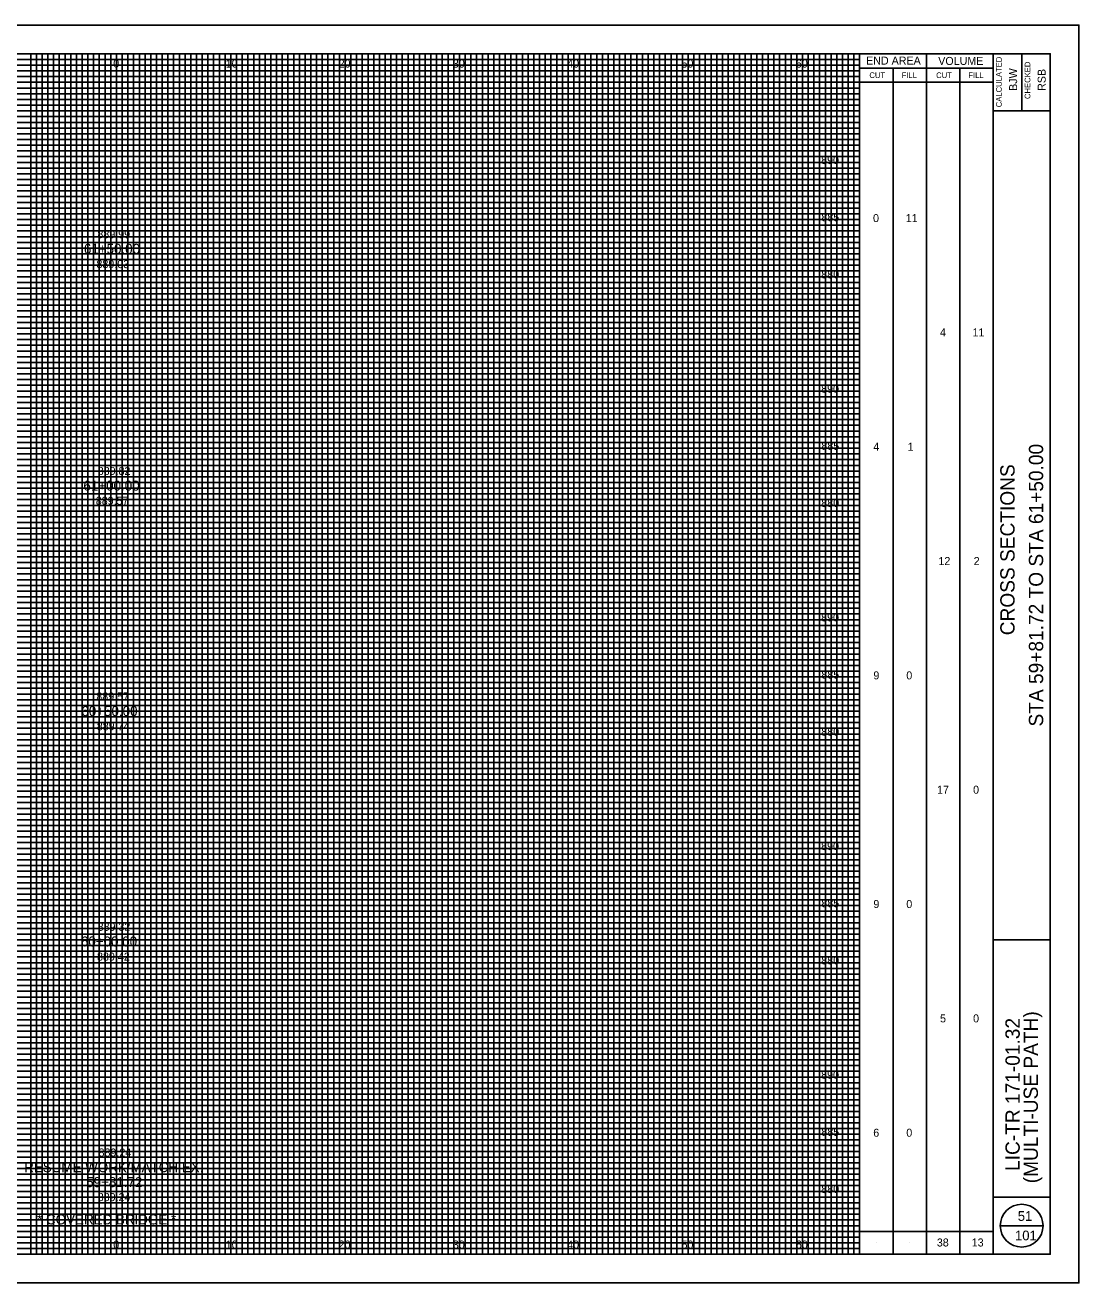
# Model space of a CAD drawing. Extents: x -10 to 160, y -2 to 222.
# Drawn here: x 67.8 to 160, y -2.5 to 107.5 of the extents above; entities that cross this region are included whole.
import ezdxf

# ---------------------------------------------------------------- set-up
doc = ezdxf.new("R2010")
doc.units = 0
for name, color, linetype in [('GK_Cells', 7, 'Continuous'), ('GK_Patterns', 7, 'Continuous'), ('SH_Cut_Line', 7, 'Continuous'), ('TX_P_10', 7, 'Continuous'), ('TX_X_10', 7, 'Continuous'), ('XS_P_Pavt_Surface', 7, 'Continuous'), ('XS_P_Text_Info', 7, 'Continuous'), ('XS_X_Ground_Line', 7, 'Continuous')]:
    doc.layers.add(name, color=color, linetype=linetype)

msp = doc.modelspace()

# ---------------------------------------------------------------- linework, layer by layer
at = {"layer": 'GK_Cells'}
msp.add_lwpolyline([(-10, -2.5), (160, -2.5), (160, 107.5), (-10, 107.5)], close=True, dxfattribs=at)
at = {"layer": 'TX_P_10'}
for p, q in [((140.83, 0), (140.83, 105)), ((146.67, 0), (146.67, 105)), ((140.83, 103.75), (152.5, 103.75)), ((143.75, 0), (143.75, 103.75)), ((149.58, 0), (149.58, 103.75)), ((140.83, 102.5), (152.5, 102.5)), ((153.12, 2.5), (156.88, 2.5)), ((140.83, 2), (152.5, 2)), ((142.29, 1), (142.29, 1)), ((145.21, 1), (145.21, 1)), ((148.12, 1), (148.12, 1)), ((151.04, 1), (151.04, 1))]:
    msp.add_line(p, q, dxfattribs=at)
msp.add_circle((155, 2.5), 1.87, dxfattribs=at)
at = {"layer": 'TX_X_10'}
for p, q in [((70.83, 0), (70.83, 105)), ((75.83, 0), (75.83, 105)), ((80.83, 0), (80.83, 105)), ((85.83, 0), (85.83, 105)), ((90.83, 0), (90.83, 105)), ((95.83, 0), (95.83, 105)), ((100.83, 0), (100.83, 105)), ((105.83, 0), (105.83, 105)), ((110.83, 0), (110.83, 105)), ((115.83, 0), (115.83, 105)), ((120.83, 0), (120.83, 105)), ((125.83, 0), (125.83, 105)), ((130.83, 0), (130.83, 105)), ((135.83, 0), (135.83, 105)), ((5.83, 100), (140.83, 100)), ((5.83, 95), (140.83, 95)), ((5.83, 90), (140.83, 90)), ((5.83, 85), (140.83, 85)), ((5.83, 80), (140.83, 80)), ((5.83, 75), (140.83, 75)), ((5.83, 70), (140.83, 70)), ((5.83, 65), (140.83, 65)), ((5.83, 60), (140.83, 60)), ((5.83, 55), (140.83, 55)), ((5.83, 50), (140.83, 50)), ((5.83, 45), (140.83, 45)), ((5.83, 40), (140.83, 40)), ((5.83, 35), (140.83, 35)), ((5.83, 30), (140.83, 30)), ((5.83, 25), (140.83, 25)), ((5.83, 20), (140.83, 20)), ((5.83, 15), (140.83, 15)), ((5.83, 10), (140.83, 10)), ((5.83, 5), (140.83, 5))]:
    msp.add_line(p, q, dxfattribs=at)
at = {"layer": 'XS_P_Pavt_Surface'}
for p, q in [((152.5, 0), (152.5, 105)), ((155, 105), (155, 100)), ((152.5, 100), (157.5, 100)), ((152.5, 27.5), (157.5, 27.5)), ((152.5, 5), (157.5, 5))]:
    msp.add_line(p, q, dxfattribs=at)
msp.add_lwpolyline([(0, 105), (157.5, 105), (157.5, 0), (0, 0)], close=True, dxfattribs=at)
at = {"layer": 'XS_X_Ground_Line'}
for p, q in [((68.33, 0), (68.33, 105)), ((68.83, 0), (68.83, 105)), ((69.33, 0), (69.33, 105)), ((69.83, 0), (69.83, 105)), ((70.33, 0), (70.33, 105)), ((71.33, 0), (71.33, 105)), ((71.83, 0), (71.83, 105)), ((72.33, 0), (72.33, 105)), ((72.83, 0), (72.83, 105)), ((73.33, 0), (73.33, 105)), ((73.83, 0), (73.83, 105)), ((74.33, 0), (74.33, 105)), ((74.83, 0), (74.83, 105)), ((75.33, 0), (75.33, 105)), ((76.33, 0), (76.33, 105)), ((76.83, 0), (76.83, 105)), ((77.33, 0), (77.33, 105)), ((77.83, 0), (77.83, 105)), ((78.33, 0), (78.33, 105)), ((78.83, 0), (78.83, 105)), ((79.33, 0), (79.33, 105)), ((79.83, 0), (79.83, 105)), ((80.33, 0), (80.33, 105)), ((81.33, 0), (81.33, 105)), ((81.83, 0), (81.83, 105)), ((82.33, 0), (82.33, 105)), ((82.83, 0), (82.83, 105)), ((83.33, 0), (83.33, 105)), ((83.83, 0), (83.83, 105)), ((84.33, 0), (84.33, 105)), ((84.83, 0), (84.83, 105)), ((85.33, 0), (85.33, 105)), ((86.33, 0), (86.33, 105)), ((86.83, 0), (86.83, 105)), ((87.33, 0), (87.33, 105)), ((87.83, 0), (87.83, 105)), ((88.33, 0), (88.33, 105)), ((88.83, 0), (88.83, 105)), ((89.33, 0), (89.33, 105)), ((89.83, 0), (89.83, 105)), ((90.33, 0), (90.33, 105)), ((91.33, 0), (91.33, 105)), ((91.83, 0), (91.83, 105)), ((92.33, 0), (92.33, 105)), ((92.83, 0), (92.83, 105)), ((93.33, 0), (93.33, 105)), ((93.83, 0), (93.83, 105)), ((94.33, 0), (94.33, 105)), ((94.83, 0), (94.83, 105)), ((95.33, 0), (95.33, 105)), ((96.33, 0), (96.33, 105)), ((96.83, 0), (96.83, 105)), ((97.33, 0), (97.33, 105)), ((97.83, 0), (97.83, 105)), ((98.33, 0), (98.33, 105)), ((98.83, 0), (98.83, 105)), ((99.33, 0), (99.33, 105)), ((99.83, 0), (99.83, 105)), ((100.33, 0), (100.33, 105)), ((101.33, 0), (101.33, 105)), ((101.83, 0), (101.83, 105)), ((102.33, 0), (102.33, 105)), ((102.83, 0), (102.83, 105)), ((103.33, 0), (103.33, 105)), ((103.83, 0), (103.83, 105)), ((104.33, 0), (104.33, 105)), ((104.83, 0), (104.83, 105)), ((105.33, 0), (105.33, 105)), ((106.33, 0), (106.33, 105)), ((106.83, 0), (106.83, 105)), ((107.33, 0), (107.33, 105)), ((107.83, 0), (107.83, 105)), ((108.33, 0), (108.33, 105)), ((108.83, 0), (108.83, 105)), ((109.33, 0), (109.33, 105)), ((109.83, 0), (109.83, 105)), ((110.33, 0), (110.33, 105)), ((111.33, 0), (111.33, 105)), ((111.83, 0), (111.83, 105)), ((112.33, 0), (112.33, 105)), ((112.83, 0), (112.83, 105)), ((113.33, 0), (113.33, 105)), ((113.83, 0), (113.83, 105)), ((114.33, 0), (114.33, 105)), ((114.83, 0), (114.83, 105)), ((115.33, 0), (115.33, 105)), ((116.33, 0), (116.33, 105)), ((116.83, 0), (116.83, 105)), ((117.33, 0), (117.33, 105)), ((117.83, 0), (117.83, 105)), ((118.33, 0), (118.33, 105)), ((118.83, 0), (118.83, 105)), ((119.33, 0), (119.33, 105)), ((119.83, 0), (119.83, 105)), ((120.33, 0), (120.33, 105)), ((121.33, 0), (121.33, 105)), ((121.83, 0), (121.83, 105)), ((122.33, 0), (122.33, 105)), ((122.83, 0), (122.83, 105)), ((123.33, 0), (123.33, 105)), ((123.83, 0), (123.83, 105)), ((124.33, 0), (124.33, 105)), ((124.83, 0), (124.83, 105)), ((125.33, 0), (125.33, 105)), ((126.33, 0), (126.33, 105)), ((126.83, 0), (126.83, 105)), ((127.33, 0), (127.33, 105)), ((127.83, 0), (127.83, 105)), ((128.33, 0), (128.33, 105)), ((128.83, 0), (128.83, 105)), ((129.33, 0), (129.33, 105)), ((129.83, 0), (129.83, 105)), ((130.33, 0), (130.33, 105)), ((131.33, 0), (131.33, 105)), ((131.83, 0), (131.83, 105)), ((132.33, 0), (132.33, 105)), ((132.83, 0), (132.83, 105)), ((133.33, 0), (133.33, 105)), ((133.83, 0), (133.83, 105)), ((134.33, 0), (134.33, 105)), ((134.83, 0), (134.83, 105)), ((135.33, 0), (135.33, 105)), ((136.33, 0), (136.33, 105)), ((136.83, 0), (136.83, 105)), ((137.33, 0), (137.33, 105)), ((137.83, 0), (137.83, 105)), ((138.33, 0), (138.33, 105)), ((138.83, 0), (138.83, 105)), ((139.33, 0), (139.33, 105)), ((139.83, 0), (139.83, 105)), ((140.33, 0), (140.33, 105)), ((5.83, 104.5), (140.83, 104.5)), ((5.83, 104), (140.83, 104)), ((5.83, 103.5), (140.83, 103.5)), ((5.83, 103), (140.83, 103)), ((5.83, 102.5), (140.83, 102.5)), ((5.83, 102), (140.83, 102)), ((5.83, 101.5), (140.83, 101.5)), ((5.83, 101), (140.83, 101)), ((5.83, 100.5), (140.83, 100.5)), ((5.83, 99.5), (140.83, 99.5)), ((5.83, 99), (140.83, 99)), ((5.83, 98.5), (140.83, 98.5)), ((5.83, 98), (140.83, 98)), ((5.83, 97.5), (140.83, 97.5)), ((5.83, 97), (140.83, 97)), ((5.83, 96.5), (140.83, 96.5)), ((5.83, 96), (140.83, 96)), ((5.83, 95.5), (140.83, 95.5)), ((5.83, 94.5), (140.83, 94.5)), ((5.83, 94), (140.83, 94)), ((5.83, 93.5), (140.83, 93.5)), ((5.83, 93), (140.83, 93)), ((5.83, 92.5), (140.83, 92.5)), ((5.83, 92), (140.83, 92)), ((5.83, 91.5), (140.83, 91.5)), ((5.83, 91), (140.83, 91)), ((5.83, 90.5), (140.83, 90.5)), ((5.83, 89.5), (140.83, 89.5)), ((5.83, 89), (140.83, 89)), ((5.83, 88.5), (140.83, 88.5)), ((5.83, 88), (140.83, 88)), ((5.83, 87.5), (140.83, 87.5)), ((5.83, 87), (140.83, 87)), ((5.83, 86.5), (140.83, 86.5)), ((5.83, 86), (140.83, 86)), ((5.83, 85.5), (140.83, 85.5)), ((5.83, 84.5), (140.83, 84.5)), ((5.83, 84), (140.83, 84)), ((5.83, 83.5), (140.83, 83.5)), ((5.83, 83), (140.83, 83)), ((5.83, 82.5), (140.83, 82.5)), ((5.83, 82), (140.83, 82)), ((5.83, 81.5), (140.83, 81.5)), ((5.83, 81), (140.83, 81)), ((5.83, 80.5), (140.83, 80.5)), ((5.83, 79.5), (140.83, 79.5)), ((5.83, 79), (140.83, 79)), ((5.83, 78.5), (140.83, 78.5)), ((5.83, 78), (140.83, 78)), ((5.83, 77.5), (140.83, 77.5)), ((5.83, 77), (140.83, 77)), ((5.83, 76.5), (140.83, 76.5)), ((5.83, 76), (140.83, 76)), ((5.83, 75.5), (140.83, 75.5)), ((5.83, 74.5), (140.83, 74.5)), ((5.83, 74), (140.83, 74)), ((5.83, 73.5), (140.83, 73.5)), ((5.83, 73), (140.83, 73)), ((5.83, 72.5), (140.83, 72.5)), ((5.83, 72), (140.83, 72)), ((5.83, 71.5), (140.83, 71.5)), ((5.83, 71), (140.83, 71)), ((5.83, 70.5), (140.83, 70.5)), ((5.83, 69.5), (140.83, 69.5)), ((5.83, 69), (140.83, 69)), ((5.83, 68.5), (140.83, 68.5)), ((5.83, 68), (140.83, 68)), ((5.83, 67.5), (140.83, 67.5)), ((5.83, 67), (140.83, 67)), ((5.83, 66.5), (140.83, 66.5)), ((5.83, 66), (140.83, 66)), ((5.83, 65.5), (140.83, 65.5)), ((5.83, 64.5), (140.83, 64.5)), ((5.83, 64), (140.83, 64)), ((5.83, 63.5), (140.83, 63.5)), ((5.83, 63), (140.83, 63)), ((5.83, 62.5), (140.83, 62.5)), ((5.83, 62), (140.83, 62)), ((5.83, 61.5), (140.83, 61.5)), ((5.83, 61), (140.83, 61)), ((5.83, 60.5), (140.83, 60.5)), ((5.83, 59.5), (140.83, 59.5)), ((5.83, 59), (140.83, 59)), ((5.83, 58.5), (140.83, 58.5)), ((5.83, 58), (140.83, 58)), ((5.83, 57.5), (140.83, 57.5)), ((5.83, 57), (140.83, 57)), ((5.83, 56.5), (140.83, 56.5)), ((5.83, 56), (140.83, 56)), ((5.83, 55.5), (140.83, 55.5)), ((5.83, 54.5), (140.83, 54.5)), ((5.83, 54), (140.83, 54)), ((5.83, 53.5), (140.83, 53.5)), ((5.83, 53), (140.83, 53)), ((5.83, 52.5), (140.83, 52.5)), ((5.83, 52), (140.83, 52)), ((5.83, 51.5), (140.83, 51.5)), ((5.83, 51), (140.83, 51)), ((5.83, 50.5), (140.83, 50.5)), ((5.83, 49.5), (140.83, 49.5)), ((5.83, 49), (140.83, 49)), ((5.83, 48.5), (140.83, 48.5)), ((5.83, 48), (140.83, 48)), ((5.83, 47.5), (140.83, 47.5)), ((5.83, 47), (140.83, 47)), ((5.83, 46.5), (140.83, 46.5)), ((5.83, 46), (140.83, 46)), ((5.83, 45.5), (140.83, 45.5)), ((5.83, 44.5), (140.83, 44.5)), ((5.83, 44), (140.83, 44)), ((5.83, 43.5), (140.83, 43.5)), ((5.83, 43), (140.83, 43)), ((5.83, 42.5), (140.83, 42.5)), ((5.83, 42), (140.83, 42)), ((5.83, 41.5), (140.83, 41.5)), ((5.83, 41), (140.83, 41)), ((5.83, 40.5), (140.83, 40.5)), ((5.83, 39.5), (140.83, 39.5)), ((5.83, 39), (140.83, 39)), ((5.83, 38.5), (140.83, 38.5)), ((5.83, 38), (140.83, 38)), ((5.83, 37.5), (140.83, 37.5)), ((5.83, 37), (140.83, 37)), ((5.83, 36.5), (140.83, 36.5)), ((5.83, 36), (140.83, 36)), ((5.83, 35.5), (140.83, 35.5)), ((5.83, 34.5), (140.83, 34.5)), ((5.83, 34), (140.83, 34)), ((5.83, 33.5), (140.83, 33.5)), ((5.83, 33), (140.83, 33)), ((5.83, 32.5), (140.83, 32.5)), ((5.83, 32), (140.83, 32)), ((5.83, 31.5), (140.83, 31.5)), ((5.83, 31), (140.83, 31)), ((5.83, 30.5), (140.83, 30.5)), ((5.83, 29.5), (140.83, 29.5)), ((5.83, 29), (140.83, 29)), ((5.83, 28.5), (140.83, 28.5)), ((5.83, 28), (140.83, 28)), ((5.83, 27.5), (140.83, 27.5)), ((5.83, 27), (140.83, 27)), ((5.83, 26.5), (140.83, 26.5)), ((5.83, 26), (140.83, 26)), ((5.83, 25.5), (140.83, 25.5)), ((5.83, 24.5), (140.83, 24.5)), ((5.83, 24), (140.83, 24)), ((5.83, 23.5), (140.83, 23.5)), ((5.83, 23), (140.83, 23)), ((5.83, 22.5), (140.83, 22.5)), ((5.83, 22), (140.83, 22)), ((5.83, 21.5), (140.83, 21.5)), ((5.83, 21), (140.83, 21)), ((5.83, 20.5), (140.83, 20.5)), ((5.83, 19.5), (140.83, 19.5)), ((5.83, 19), (140.83, 19)), ((5.83, 18.5), (140.83, 18.5)), ((5.83, 18), (140.83, 18)), ((5.83, 17.5), (140.83, 17.5)), ((5.83, 17), (140.83, 17)), ((5.83, 16.5), (140.83, 16.5)), ((5.83, 16), (140.83, 16)), ((5.83, 15.5), (140.83, 15.5)), ((5.83, 14.5), (140.83, 14.5)), ((5.83, 14), (140.83, 14)), ((5.83, 13.5), (140.83, 13.5)), ((5.83, 13), (140.83, 13)), ((5.83, 12.5), (140.83, 12.5)), ((5.83, 12), (140.83, 12)), ((5.83, 11.5), (140.83, 11.5)), ((5.83, 11), (140.83, 11)), ((5.83, 10.5), (140.83, 10.5)), ((5.83, 9.5), (140.83, 9.5)), ((5.83, 9), (140.83, 9)), ((5.83, 8.5), (140.83, 8.5)), ((5.83, 8), (140.83, 8)), ((5.83, 7.5), (140.83, 7.5)), ((5.83, 7), (140.83, 7)), ((5.83, 6.5), (140.83, 6.5)), ((5.83, 6), (140.83, 6)), ((5.83, 5.5), (140.83, 5.5)), ((5.83, 4.5), (140.83, 4.5)), ((5.83, 4), (140.83, 4)), ((5.83, 3.5), (140.83, 3.5)), ((5.83, 3), (140.83, 3)), ((5.83, 2.5), (140.83, 2.5)), ((5.83, 2), (140.83, 2)), ((5.83, 1.5), (140.83, 1.5)), ((5.83, 1), (140.83, 1)), ((5.83, 0.5), (140.83, 0.5))]:
    msp.add_line(p, q, dxfattribs=at)

# ---------------------------------------------------------------- texts
at = {"layer": 'GK_Patterns'}
for s, height, p in [('0', 0.7, (75.55, 103.79)), ('0', 0.7, (75.55, 103.79)), ('10', 0.7, (85.39, 103.79)), ('20', 0.7, (95.26, 103.79)), ('30', 0.7, (105.25, 103.79)), ('40', 0.7, (115.25, 103.79)), ('50', 0.7, (125.25, 103.79)), ('60', 0.7, (135.25, 103.79)), ('890', 0.7, (137.46, 95.35)), ('885', 0.7, (137.48, 90.35)), ('0', 0.7, (142, 90.28)), ('11', 0.7, (144.86, 90.28)), ('61+50.00', 0.875, (72.98, 87.5)), ('880', 0.7, (137.47, 85.35)), ('4', 0.7, (147.85, 80.28)), ('11', 0.7, (150.7, 80.28)), ('890', 0.7, (137.46, 75.35)), ('885', 0.7, (137.48, 70.35)), ('4', 0.7, (142.02, 70.28)), ('1', 0.7, (145.03, 70.28)), ('61+00.00', 0.875, (72.94, 66.79)), ('880', 0.7, (137.47, 65.35)), ('12', 0.7, (147.72, 60.28)), ('2', 0.7, (150.8, 60.28)), ('890', 0.7, (137.46, 55.35)), ('885', 0.7, (137.48, 50.35)), ('9', 0.7, (142.03, 50.28)), ('0', 0.7, (144.91, 50.28)), ('60+50.00', 0.875, (72.76, 47.07)), ('880', 0.7, (137.47, 45.35)), ('17', 0.7, (147.6, 40.28)), ('0', 0.7, (150.75, 40.28)), ('890', 0.7, (137.46, 35.35)), ('885', 0.7, (137.48, 30.35)), ('9', 0.7, (142.03, 30.28)), ('0', 0.7, (144.91, 30.28)), ('60+00.00', 0.875, (72.72, 26.92)), ('880', 0.7, (137.47, 25.35)), ('5', 0.7, (147.86, 20.28)), ('0', 0.7, (150.75, 20.28)), ('890', 0.7, (137.46, 15.35)), ('885', 0.7, (137.48, 10.35)), ('6', 0.7, (142.02, 10.28)), ('0', 0.7, (144.91, 10.28)), ('RESUME WORK/MATCH EX.', 0.875, (67.76, 7.18)), ('59+81.72', 0.875, (73.18, 5.87)), ('880', 0.7, (137.47, 5.35)), ('* COVERED BRIDGE *', 0.875, (68.89, 2.61)), ('0', 0.7, (75.55, 0.5)), ('0', 0.7, (75.55, 0.5)), ('10', 0.7, (85.39, 0.5)), ('20', 0.7, (95.26, 0.5)), ('30', 0.7, (105.25, 0.5)), ('40', 0.7, (115.25, 0.5)), ('50', 0.7, (125.25, 0.5)), ('60', 0.7, (135.25, 0.5)), ('38', 0.7, (147.58, 0.68)), ('13', 0.7, (150.63, 0.68))]:
    msp.add_text(s, height=height, dxfattribs=at).set_placement(p)
at = {"layer": 'SH_Cut_Line'}
for s, p in [('889.03', (74.08, 86.25)), ('889.57', (74.02, 65.55)), ('889.74', (74.11, 45.83)), ('889.42', (74.13, 25.68)), ('889.24', (74.19, 4.65))]:
    msp.add_text(s, height=0.7, dxfattribs=at).set_placement(p)
at = {"layer": 'TX_P_10'}
for s, height, p in [('END AREA', 0.7, (141.39, 104.05)), ('VOLUME', 0.7, (147.7, 104.02)), ('CUT', 0.5, (141.68, 102.87)), ('FILL', 0.5, (144.5, 102.87)), ('CUT', 0.5, (147.52, 102.87)), ('FILL', 0.5, (150.34, 102.87)), ('51', 0.85, (154.66, 2.92)), ('101', 0.85, (154.42, 1.22))]:
    msp.add_text(s, height=height, dxfattribs=at).set_placement(p)
for s, height, p in [('CALCULATED', 0.5, (153.26, 100.32)), ('BJW', 0.7, (154.6, 101.75)), ('CHECKED', 0.5, (155.76, 101.04)), ('RSB', 0.7, (157.1, 101.75)), ('STA 59+81.72 TO STA 61+50.00', 1.25, (156.88, 46.16)), ('CROSS SECTIONS', 1.25, (154.38, 54.14)), ('(MULTI-USE PATH)', 1.25, (156.42, 6.21)), ('LIC-TR 171-01.32', 1.25, (154.83, 7.29))]:
    msp.add_text(s, height=height, rotation=90, dxfattribs=at).set_placement(p)
at = {"layer": 'XS_P_Text_Info'}
for s, p in [('889.99', (74.16, 88.87)), ('889.82', (74.19, 68.16)), ('889.57', (74.07, 48.44)), ('889.32', (74.18, 28.29)), ('889.24', (74.26, 8.55))]:
    msp.add_text(s, height=0.7, dxfattribs=at).set_placement(p)

doc.saveas('drawing.dxf')
